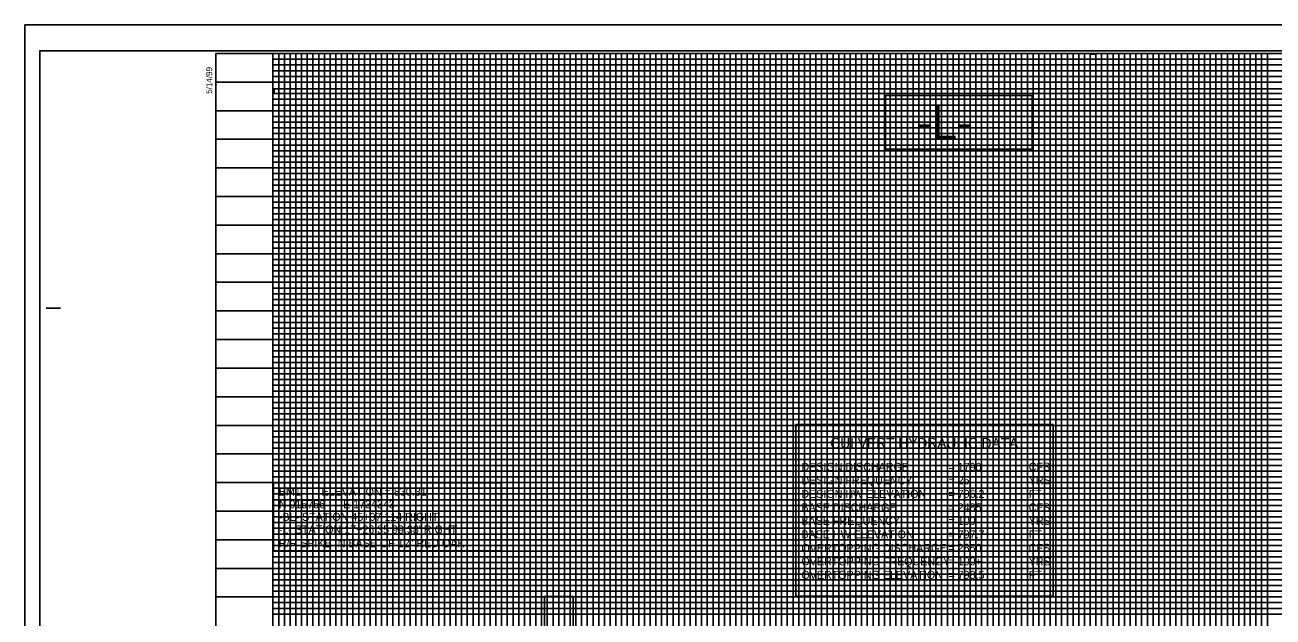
# Model space of a CAD drawing. Extents: x 573566 to 575250, y -53414 to -52314.
# Drawn here: x 573566 to 574658, y -52832 to -52314 of the extents above; entities that cross this region are included whole.
import ezdxf

# ---------------------------------------------------------------- set-up
doc = ezdxf.new("R2010")
doc.units = 0
for name, color, linetype in [('Prop Grid Mask', 7, 'Continuous'), ('Prop PFL Culvert Hydraulic Data Label CELL', 7, 'Continuous'), ('Prop PFL Text', 7, 'Continuous'), ('Prop VPI Label', 7, 'Continuous'), ('Sheet Cutting Line CELL', 7, 'Continuous'), ('Sheet DOT Grid CELL', 7, 'Continuous'), ('Sheet Layout Profile Border', 7, 'Continuous'), ('Sheet Plot Border Inside CELL', 7, 'Continuous'), ('Sheet Plot Border Outside CELL', 7, 'Continuous'), ('Sheet Profile CELL', 7, 'Continuous'), ('Sheet Profile Grid Major CELL', 7, 'Continuous'), ('Sheet Profile Grid Middle CELL', 7, 'Continuous'), ('Sheet Profile Grid Minor CELL', 7, 'Continuous')]:
    doc.layers.add(name, color=color, linetype=linetype)

msp = doc.modelspace()

# ---------------------------------------------------------------- linework, layer by layer
at = {"layer": 'Prop Grid Mask'}
for points in [[(574319.2, -52375.7), (574447.4, -52375.7), (574447.4, -52422.7), (574319.2, -52422.7)], [(574240.8, -52813.3), (574465.8, -52813.3), (574465.8, -52663.3), (574240.8, -52663.3)], [(573783.8, -52714.4), (573982.8, -52714.4), (573982.8, -52773.6), (573783.8, -52773.6)], [(574045.9, -52982.5), (574020.8, -52982.5), (574020.8, -52813.5), (574045.9, -52813.5)]]:
    msp.add_lwpolyline(points, close=True, dxfattribs=at)
at = {"layer": 'Prop VPI Label'}
msp.add_line((574033.3, -52993.8), (574033.3, -52817.1), dxfattribs=at)
at = {"layer": 'Sheet Cutting Line CELL'}
for p, q in [((575250.3, -52314), (573566.3, -52314)), ((573566.3, -52314), (573566.3, -53414))]:
    msp.add_line(p, q, dxfattribs=at)
at = {"layer": 'Sheet DOT Grid CELL'}
for p, q in [((573783.3, -52339), (573783.3, -53364)), ((573833.3, -52339), (573833.3, -53364)), ((573883.3, -52339), (573883.3, -53364)), ((573933.3, -52339), (573933.3, -53364)), ((573983.3, -52339), (573983.3, -53364)), ((574033.3, -52339), (574033.3, -53364)), ((574083.3, -52339), (574083.3, -53364)), ((574133.3, -52339), (574133.3, -53364)), ((574183.3, -52339), (574183.3, -53364)), ((574233.3, -52339), (574233.3, -53364)), ((574283.3, -52339), (574283.3, -53364)), ((574333.3, -52339), (574333.3, -53364)), ((574383.3, -52339), (574383.3, -53364)), ((574433.3, -52339), (574433.3, -53364)), ((574483.3, -52339), (574483.3, -53364)), ((574533.3, -52339), (574533.3, -53364)), ((574583.3, -52339), (574583.3, -53364)), ((574633.3, -52339), (574633.3, -53364)), ((573733.3, -52364), (575033.3, -52364)), ((573733.3, -52414), (575033.3, -52414)), ((573733.3, -52464), (575033.3, -52464)), ((573733.3, -52514), (575233.3, -52514)), ((573733.3, -52564), (575233.3, -52564)), ((573733.3, -52614), (575233.3, -52614)), ((573733.3, -52664), (575233.3, -52664)), ((573733.3, -52714), (575233.3, -52714)), ((573733.3, -52764), (575233.3, -52764)), ((573733.3, -52814), (575233.3, -52814))]:
    msp.add_line(p, q, dxfattribs=at)
at = {"layer": 'Sheet Layout Profile Border'}
msp.add_lwpolyline([(573783.3, -52339), (573783.3, -53364), (575183.3, -53364), (575183.3, -52476.6), (575033.3, -52476.6), (575033.3, -52339)], close=True, dxfattribs=at)
at = {"layer": 'Sheet Plot Border Inside CELL'}
msp.add_lwpolyline([(575245.8, -52336.5), (573579.3, -52336.5), (573579.3, -53391.6), (575245.8, -53391.6)], close=True, dxfattribs=at)
at = {"layer": 'Sheet Plot Border Outside CELL'}
msp.add_lwpolyline([(575250.3, -52314), (573566.3, -52314), (573566.3, -53414), (575250.3, -53414)], close=True, dxfattribs=at)
at = {"layer": 'Sheet Profile CELL'}
msp.add_line((573584.8, -52561.5), (573597.3, -52561.5), dxfattribs=at)
msp.add_lwpolyline([(575233.3, -52339), (573733.3, -52339), (573733.3, -53389), (575233.3, -53389)], close=True, dxfattribs=at)
at = {"layer": 'Sheet Profile Grid Major CELL'}
for points in [[(573733.3, -52339), (573783.3, -52339), (573783.3, -53364)], [(573833.3, -53364), (573833.3, -52339), (573883.3, -52339), (573883.3, -53364)], [(573933.3, -53364), (573933.3, -52339), (573983.3, -52339), (573983.3, -53364)], [(574033.3, -53364), (574033.3, -52339), (574083.3, -52339), (574083.3, -53364)], [(574133.3, -53364), (574133.3, -52339), (574183.3, -52339), (574183.3, -53364)], [(574233.3, -53364), (574233.3, -52339), (574283.3, -52339), (574283.3, -53364)], [(574333.3, -53364), (574333.3, -52339), (574383.3, -52339), (574383.3, -53364)], [(574433.3, -53364), (574433.3, -52339), (574483.3, -52339), (574483.3, -53364)], [(574533.3, -53364), (574533.3, -52339), (574583.3, -52339), (574583.3, -53364)], [(574633.3, -53364), (574633.3, -52339), (574683.3, -52339)], [(575033.3, -52414), (573733.4, -52414), (573733.4, -52364.1), (575033.3, -52364.1)], [(575233.3, -52514), (573733.3, -52514), (573733.3, -52464), (575033.3, -52464)], [(575233.3, -52614), (573733.3, -52614), (573733.3, -52564), (575233.3, -52564)], [(575233.3, -52714), (573733.3, -52714), (573733.3, -52664), (575233.3, -52664)], [(575233.3, -52814), (573733.3, -52814), (573733.3, -52764), (575233.3, -52764)]]:
    msp.add_lwpolyline(points, dxfattribs=at)
at = {"layer": 'Sheet Profile Grid Middle CELL'}
for points in [[(573808.3, -53364), (573808.3, -52339), (573858.3, -52339), (573858.3, -53364)], [(573908.3, -53364), (573908.3, -52339), (573958.3, -52339), (573958.3, -53364)], [(574008.3, -53364), (574008.3, -52339), (574058.3, -52339), (574058.3, -53364)], [(574108.3, -53364), (574108.3, -52339), (574158.3, -52339), (574158.3, -53364)], [(574208.3, -53364), (574208.3, -52339), (574258.3, -52339), (574258.3, -53364)], [(574308.3, -53364), (574308.3, -52339), (574358.3, -52339), (574358.3, -53364)], [(574408.3, -53364), (574408.3, -52339), (574458.3, -52339), (574458.3, -53364)], [(574508.3, -53364), (574508.3, -52339), (574558.3, -52339), (574558.3, -53364)], [(574608.3, -53364), (574608.3, -52339), (574658.3, -52339)], [(573733.3, -52389), (575033.3, -52389)], [(575033.3, -52439), (573733.3, -52439), (573733.3, -52489.1), (575233.3, -52489.1)], [(575233.3, -52539), (573733.3, -52539), (573733.3, -52589), (575233.3, -52589)], [(575233.3, -52639), (573733.3, -52639), (573733.3, -52689), (575233.3, -52689)], [(575233.3, -52739), (573733.3, -52739), (573733.3, -52789), (575233.3, -52789)]]:
    msp.add_lwpolyline(points, dxfattribs=at)
at = {"layer": 'Sheet Profile Grid Minor CELL'}
for p, q in [((575183.3, -52519), (573783.3, -52519)), ((573783.3, -52519), (573783.3, -52524)), ((573783.3, -52524), (575183.3, -52524)), ((575183.3, -52544), (573783.3, -52544))]:
    msp.add_line(p, q, dxfattribs=at)
for points in [[(573788.3, -52339), (573793.3, -52339), (573798.3, -52339), (573803.3, -52339), (573813.3, -52339), (573780.3, -52339), (573785.3, -52339), (573743.3, -52339), (573748.3, -52339), (573753.3, -52339), (573763.3, -52339), (573768.3, -52339), (573773.3, -52339), (573778.3, -52339), (573788.3, -52339), (573788.3, -53364)], [(575033.3, -52344), (573783.3, -52344), (573783.3, -52349), (575033.3, -52349)], [(573793.3, -53364), (573793.3, -52339), (573798.3, -52339), (573798.3, -53364)], [(573803.3, -53364), (573803.3, -52339), (573813.3, -52339), (573813.3, -53364)], [(573818.3, -53364), (573818.3, -52339), (573823.3, -52339), (573823.3, -53364)], [(573828.3, -53364), (573828.3, -52339), (573838.3, -52339), (573838.3, -53364)], [(573843.3, -53364), (573843.3, -52339), (573848.3, -52339), (573848.3, -53364)], [(573853.3, -53364), (573853.3, -52339), (573863.3, -52339), (573863.3, -53364)], [(573868.3, -53364), (573868.3, -52339), (573873.3, -52339), (573873.3, -53364)], [(573878.3, -53364), (573878.3, -52339), (573888.3, -52339), (573888.3, -53364)], [(573893.3, -53364), (573893.3, -52339), (573898.3, -52339), (573898.3, -53364)], [(573903.3, -53364), (573903.3, -52339), (573913.3, -52339), (573913.3, -53364)], [(573918.3, -53364), (573918.3, -52339), (573923.3, -52339), (573923.3, -53364)], [(573928.3, -53364), (573928.3, -52339), (573938.3, -52339), (573938.3, -53364)], [(573943.3, -53364), (573943.3, -52339), (573948.3, -52339), (573948.3, -53364)], [(573953.3, -53364), (573953.3, -52339), (573963.3, -52339), (573963.3, -53364)], [(573968.3, -53364), (573968.3, -52339), (573973.3, -52339), (573973.3, -53364)], [(573978.3, -53364), (573978.3, -52339), (573988.3, -52339), (573988.3, -53364)], [(573993.3, -53364), (573993.3, -52339), (573993.3, -52339), (573998.3, -52339), (573998.3, -53364)], [(574003.3, -53364), (574003.3, -52339), (574013.3, -52339), (574013.3, -53364)], [(574018.3, -53364), (574018.3, -52339), (574023.3, -52339), (574023.3, -53364)], [(574028.3, -53364), (574028.3, -52339), (574038.3, -52339), (574038.3, -53364)], [(574043.3, -53364), (574043.3, -52339), (574048.3, -52339), (574048.3, -53364)], [(574053.3, -53364), (574053.3, -52339), (574063.3, -52339), (574063.3, -53364)], [(574068.3, -53364), (574068.3, -52339), (574073.3, -52339), (574073.3, -53364)], [(574078.3, -53364), (574078.3, -52339), (574088.3, -52339), (574088.3, -53364)], [(574093.3, -53364), (574093.3, -52339), (574098.3, -52339), (574098.3, -53364)], [(574103.3, -53364), (574103.3, -52339), (574113.3, -52339), (574113.3, -53364)], [(574118.3, -52339), (574118.3, -53364), (574123.3, -53364), (574123.3, -52339)], [(574118.3, -52339.6), (574118.3, -53364), (574123.3, -53364), (574123.3, -52339.6)], [(574128.3, -53364), (574128.3, -52339), (574138.3, -52339), (574138.3, -53364)], [(574143.3, -53364), (574143.3, -52339), (574148.3, -52339), (574148.3, -53364)], [(574153.3, -53364), (574153.3, -52339), (574163.3, -52339), (574163.3, -53364)], [(574168.3, -53364), (574168.3, -52339), (574173.3, -52339), (574173.3, -53364)], [(574178.3, -53364), (574178.3, -52339), (574188.3, -52339), (574188.3, -53364)], [(574193.3, -53364), (574193.3, -52339), (574198.3, -52339), (574198.3, -53364)], [(574203.3, -53364), (574203.3, -52339), (574213.3, -52339), (574213.3, -53364)], [(574218.3, -53364), (574218.3, -52339), (574223.3, -52339), (574223.3, -53364)], [(574228.3, -53364), (574228.3, -52339), (574238.3, -52339), (574238.3, -53364)], [(574243.3, -53364), (574243.3, -52339), (574248.3, -52339), (574248.3, -53364)], [(574253.3, -53364), (574253.3, -52339), (574263.3, -52339), (574263.3, -53364)], [(574268.3, -52339), (574268.3, -53364), (574273.3, -53364), (574273.3, -52339), (574278.3, -52339), (574278.3, -53364), (574288.3, -53364), (574288.3, -52339), (574293.3, -52339), (574293.3, -53364), (574298.3, -53364), (574298.3, -52339), (574303.3, -52339), (574303.3, -53364)], [(574313.3, -53364), (574313.3, -52339), (574318.3, -52339), (574318.3, -53364)], [(574323.3, -53364), (574323.3, -52339), (574328.3, -52339), (574328.3, -53364)], [(574338.3, -53364), (574338.3, -52339), (574343.3, -52339), (574343.3, -53364)], [(574348.3, -53364), (574348.3, -52339), (574353.3, -52339), (574353.3, -53364)], [(574363.3, -53364), (574363.3, -52339), (574368.3, -52339), (574368.3, -53364)], [(574373.3, -53364), (574373.3, -52339), (574378.3, -52339), (574378.3, -53364)], [(574388.3, -53364), (574388.3, -52339), (574393.3, -52339), (574393.3, -53364)], [(574398.3, -53364), (574398.3, -52339), (574403.3, -52339), (574403.3, -53364)], [(574413.3, -53364), (574413.3, -52339), (574418.3, -52339), (574418.3, -53364)], [(574423.3, -53364), (574423.3, -52339), (574428.3, -52339), (574428.3, -53364)], [(574438.3, -53364), (574438.3, -52339), (574443.3, -52339), (574443.3, -53364)], [(574448.3, -53364), (574448.3, -52339), (574453.3, -52339), (574453.3, -53364)], [(574463.3, -53364), (574463.3, -52339), (574468.3, -52339), (574468.3, -53364)], [(574473.3, -53364), (574473.3, -52339), (574478.3, -52339), (574478.3, -53364)], [(574488.3, -53364), (574488.3, -52339), (574493.3, -52339), (574493.3, -53364)], [(574498.3, -53364), (574498.3, -52339.6), (574503.3, -52339.6), (574503.3, -53364)], [(574513.3, -53364), (574513.3, -52339), (574518.3, -52339), (574518.3, -53364)], [(574523.3, -53364), (574523.3, -52339), (574528.3, -52339), (574528.3, -53364)], [(574538.3, -53364), (574538.3, -52339), (574543.3, -52339), (574543.3, -53364)], [(574548.3, -53364), (574548.3, -52339), (574553.3, -52339), (574553.3, -53364)], [(574563.3, -53364), (574563.3, -52339), (574568.3, -52339), (574568.3, -53364)], [(574573.3, -53364), (574573.3, -52339), (574578.3, -52339), (574578.3, -53364)], [(574588.3, -53364), (574588.3, -52339), (574593.3, -52339), (574593.3, -53364)], [(574598.3, -53364), (574598.3, -52339), (574603.3, -52339), (574603.3, -53364)], [(574613.3, -53364), (574613.3, -52339), (574618.3, -52339), (574618.3, -53364)], [(574623.3, -53364), (574623.3, -52339), (574628.3, -52339), (574628.3, -53364)], [(574638.3, -53364), (574638.3, -52339), (574643.3, -52339), (574643.3, -53364)], [(574648.3, -53364), (574648.3, -52339), (574653.3, -52339), (574653.3, -53364)], [(575033.3, -52354), (573783.3, -52354), (573783.3, -52359), (575033.3, -52359)], [(575033.3, -52379), (573783.3, -52379), (573783.3, -52384), (575033.3, -52384)], [(575033.3, -52369.8), (573784.3, -52369.8), (573784.3, -52374), (575033.3, -52374)], [(575033.3, -52394), (573783.3, -52394), (573783.3, -52399), (575033.3, -52399)], [(575033.3, -52404), (573783.3, -52404), (573783.3, -52409), (575033.3, -52409)], [(575033.3, -52419), (573783.3, -52419), (573783.3, -52424), (575033.3, -52424)], [(575033.3, -52429), (573783.3, -52429), (573783.3, -52434), (575033.3, -52434)], [(575033.3, -52444), (573783.3, -52444), (573783.3, -52449), (575033.3, -52449)], [(575033.3, -52454), (573783.3, -52454), (573783.3, -52459), (575033.3, -52459)], [(575033.3, -52469), (573783.3, -52469), (573783.3, -52474), (575033.3, -52474)], [(575183.3, -52479), (573783.3, -52479), (573783.3, -52479), (573783.3, -52499), (575183.3, -52499)], [(573783.3, -52484), (575183.3, -52484)], [(575183.3, -52494), (573783.3, -52494)], [(575183.3, -52504), (573783.3, -52504), (573783.3, -52509), (575183.3, -52509)], [(575183.3, -52529), (573783.3, -52529), (573783.3, -52534), (575183.3, -52534)], [(575183.3, -52549), (573783.3, -52549), (573783.3, -52554), (575183.3, -52554)], [(575183.3, -52559), (573783.3, -52559)], [(573783.3, -52569), (575183.3, -52569)], [(575183.3, -52574), (573783.3, -52574), (573783.3, -52579), (575183.3, -52579)], [(575183.3, -52584), (573783.3, -52584), (573783.3, -52594), (575183.3, -52594)], [(575183.3, -52599), (573783.3, -52599), (573783.3, -52604), (575183.3, -52604)], [(575183.3, -52609), (573783.3, -52609), (573783.3, -52619), (575183.3, -52619)], [(575183.3, -52624), (573783.3, -52624), (573783.3, -52629), (575183.3, -52629)], [(575183.3, -52634), (573783.3, -52634), (573783.3, -52644), (575183.3, -52644)], [(575183.3, -52649), (573783.3, -52649), (573783.3, -52654), (575183.3, -52654)], [(575183.3, -52659), (573783.3, -52659), (573783.3, -52669), (575183.3, -52669)], [(575183.3, -52674), (573783.3, -52674), (573783.3, -52679), (575183.3, -52679)], [(575183.3, -52684), (573783.3, -52684), (573783.3, -52694), (575183.3, -52694)], [(575183.3, -52699), (573783.3, -52699), (573783.3, -52704), (575183.3, -52704)], [(575183.3, -52709), (573783.3, -52709), (573783.3, -52719), (575183.3, -52719)], [(575183.3, -52724), (573783.3, -52724), (573783.3, -52729), (575183.3, -52729)], [(575183.3, -52734), (573783.3, -52734), (573783.3, -52744), (575183.3, -52744)], [(575183.3, -52749), (573783.3, -52749), (573783.3, -52754), (575183.3, -52754)], [(575183.3, -52759), (573783.3, -52759), (573783.3, -52769), (575183.3, -52769)], [(575183.3, -52774), (573783.3, -52774), (573783.3, -52779), (575183.3, -52779)], [(575183.3, -52784), (573783.3, -52784), (573783.3, -52794), (575183.3, -52794)], [(575183.3, -52799), (573783.3, -52799), (573783.3, -52804), (575183.3, -52804)], [(575183.3, -52809), (573783.3, -52809), (573783.3, -52819), (575183.3, -52819)], [(575183.3, -52824), (573783.3, -52824), (573783.3, -52829), (575183.3, -52829)]]:
    msp.add_lwpolyline(points, dxfattribs=at)

# ---------------------------------------------------------------- texts
at = {"layer": 'Prop PFL Culvert Hydraulic Data Label CELL'}
for s, height, p in [('CULVERT HYDRAULIC DATA', 9, (574270.9, -52684.1)), ('DESIGN DISCHARGE', 7, (574245.6, -52703.8)), ('= 1790    ', 7, (574374.3, -52703.8)), ('CFS', 7, (574444.5, -52703.7)), ('DESIGN FREQUENCY', 7, (574245.6, -52715.6)), ('= 25 ', 7, (574374.3, -52715.6)), ('YRS', 7, (574444.5, -52715.6)), ('DESIGN HW ELEVATION', 7, (574245.6, -52727.4)), ('= 796.2   ', 7, (574374.3, -52727.4)), ('FT', 7, (574444.5, -52727.4)), ('BASE DISCHARGE', 7, (574245.6, -52739.2)), ('= 2485    ', 7, (574374.3, -52739.2)), ('CFS', 7, (574444.5, -52739.2)), ('BASE FREQUENCY', 7, (574245.6, -52751)), ('= 100', 7, (574374.3, -52751)), ('YRS', 7, (574444.5, -52751)), ('BASE HW ELEVATION', 7, (574245.6, -52762.8)), ('= 797.7   ', 7, (574374.3, -52762.8)), ('FT', 7, (574444.5, -52762.8)), ('OVERTOPPING DISCHARGE', 7, (574245.6, -52774.6)), ('= 2850    ', 7, (574374.3, -52774.6)), ('CFS', 7, (574444.5, -52774.6)), ('OVERTOPPING FREQUENCY', 7, (574245.6, -52786.4)), ('= 100+', 7, (574374.3, -52786.4)), ('YRS', 7, (574444.5, -52786.4)), ('OVERTOPPING ELEVATION', 7, (574245.6, -52798.2)), ('= 798.5   ', 7, (574374.3, -52798.2)), ('FT', 7, (574444.5, -52798.2))]:
    msp.add_text(s, height=height, dxfattribs=at).set_placement(p)
at = {"layer": 'Prop PFL Text'}
msp.add_text('-L-', height=30, dxfattribs=at).set_placement((574346.3, -52414.2))
at = {"layer": 'Prop VPI Label'}
for s, p in [("BM1       ELEVATION = 830.31'", (573788.4, -52725.5)), ('N 915756      E 1734343', (573788.4, -52736.5)), ('-BL- STATION 45+07 114 RIGHT', (573788.4, -52747.5)), ("-L- STATION 17+26.35 99.38' RIGHT", (573788.4, -52758.5)), ('R/R SPIKE IN BASE OF 12" RED OAK', (573788.4, -52770.5))]:
    msp.add_text(s, height=7, rotation=360, dxfattribs=at).set_placement(p)
at = {"layer": 'Sheet Profile CELL'}
msp.add_text('5/14/99', height=5.25, rotation=90, dxfattribs=at).set_placement((573730.1, -52374.2))

doc.saveas('drawing.dxf')
